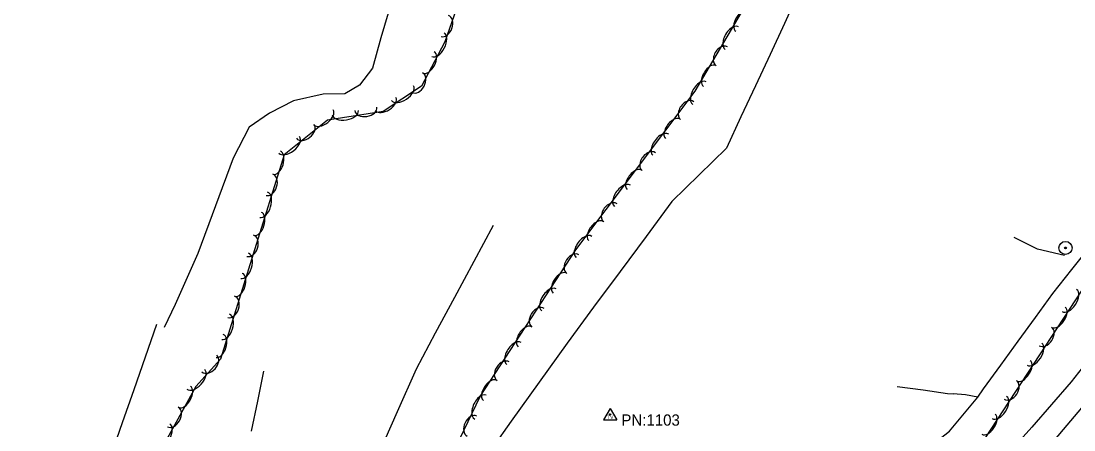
# Model space of a CAD drawing. Extents: x 1451369 to 1458940, y 1868647 to 1875095.
# Drawn here: x 1454280 to 1454748.2, y 1871820 to 1872001.9 of the extents above; entities that cross this region are included whole.
import ezdxf

# ---------------------------------------------------------------- set-up
doc = ezdxf.new("R2010")
doc.units = 0
for name, color, linetype in [('E_Const Align Station', 7, 'Continuous'), ('E_ROW Point Number', 7, 'Continuous'), ('E_Station Offset', 7, 'Continuous'), ('E_Tract Residual', 7, 'Continuous'), ('S_EDGE_PAVEMENT', 7, 'Continuous'), ('S_EXIST_ROW', 7, 'Continuous'), ('S_PAVEMENT_CROWN', 7, 'Continuous'), ('S_SECONDARY_CTL_ANNOT', 7, 'Continuous')]:
    doc.layers.add(name, color=color, linetype=linetype)

msp = doc.modelspace()

# ---------------------------------------------------------------- linework, layer by layer
at = {"layer": 'E_Const Align Station'}
for radius in [2.91, 0.411, 0.262, 0.212, 0.145, 0.0822, 0.0581]:
    msp.add_circle((1454744.49, 1871900.96), radius, dxfattribs=at)
at = {"layer": 'E_ROW Point Number'}
for points in [[(1454455.54, 1871775.31), (1454484.24, 1871834.95), (1454526.73, 1871900.15), (1454579.81, 1871970.72), (1454615.08, 1872030.7)], [(1454474.53, 1872009.99), (1454468.45, 1871992.6), (1454458.03, 1871972.85), (1454441.05, 1871961.61), (1454416.35, 1871957.74), (1454397.06, 1871942.33), (1454383.25, 1871898.18), (1454368.69, 1871851.44), (1454357.73, 1871839.38), (1454344.98, 1871816.3), (1454328.66, 1871765.24)], [(1454754.24, 1871885.99), (1454738.31, 1871861.57), (1454708.8, 1871816.51)]]:
    msp.add_lwpolyline(points, dxfattribs=at)
for centre, major_axis, ratio, start_param, end_param in [((1454468.42, 1871999.71), (1.64, 4.68), 0.683448, 3.141593, 6.283185), ((1454600.63, 1872001.94), (-2.71, -4.61), 0.540792, 3.141353, 6.282945), ((1454596.13, 1871994.3), (-2.97, -5.06), 0.550174, 3.141345, 6.282938), ((1454465.38, 1871991.33), (2.74, 5.19), 0.548524, 3.141593, 6.283185), ((1454591.67, 1871986.19), (-2.51, -4.27), 0.685428, 3.141187, 6.28278), ((1454461.25, 1871983.48), (2.49, 4.73), 0.53917, 3.141593, 6.283185), ((1454586.22, 1871977.44), (-2.71, -4.61), 0.540792, 3.141353, 6.282945), ((1454456.21, 1871974.49), (2.31, 4.38), 0.683373, 3.141593, 6.283185), ((1454449.65, 1871969.84), (4.89, 3.24), 0.548805, 3.141593, 6.283185), ((1454581.73, 1871969.8), (-2.97, -5.06), 0.550174, 3.141345, 6.282938), ((1454442.25, 1871964.94), (4.46, 2.95), 0.539446, 3.141593, 6.283185), ((1454576.25, 1871962.03), (-2.98, -3.96), 0.685311, 3.141382, 6.282975), ((1454414.57, 1871959.02), (4.18, 3.34), 0.539349, 3.141593, 6.283185), ((1454433.31, 1871962.8), (4.9, 0.77), 0.684504, 3.141593, 6.283185), ((1454424.2, 1871961.11), (5.8, 0.91), 0.549433, 3.141593, 6.283185), ((1454569.85, 1871953.96), (-3.21, -4.27), 0.540699, 3.141468, 6.283061), ((1454406.36, 1871952.8), (3.87, 3.09), 0.683599, 3.141593, 6.283185), ((1454399.29, 1871946.82), (4.59, 3.66), 0.548706, 3.141593, 6.283185), ((1454564.52, 1871946.87), (-3.53, -4.69), 0.55008, 3.141464, 6.283057), ((1454393.75, 1871938.83), (1.6, 5.1), 0.539252, 3.141593, 6.283185), ((1454559.17, 1871939.31), (-2.98, -3.96), 0.685311, 3.141382, 6.282975), ((1454552.77, 1871931.24), (-3.21, -4.27), 0.540699, 3.141468, 6.283061), ((1454390.43, 1871929.08), (1.48, 4.73), 0.683476, 3.141593, 6.283185), ((1454547.44, 1871924.15), (-3.53, -4.69), 0.55008, 3.141464, 6.283057), ((1454387.91, 1871920.16), (1.75, 5.6), 0.548607, 3.141593, 6.283185), ((1454542.08, 1871916.6), (-2.98, -3.96), 0.685311, 3.141382, 6.282975), ((1454385.26, 1871911.7), (1.6, 5.1), 0.539252, 3.141593, 6.283185), ((1454535.68, 1871908.52), (-3.21, -4.27), 0.540699, 3.141468, 6.283061), ((1454381.94, 1871901.95), (1.48, 4.73), 0.683476, 3.141593, 6.283185), ((1454530.35, 1871901.43), (-3.53, -4.69), 0.55008, 3.141464, 6.283057), ((1454379.43, 1871893.03), (1.75, 5.6), 0.548608, 3.141593, 6.283185), ((1454525.42, 1871893.77), (-2.7, -4.15), 0.685282, 3.141427, 6.283019), ((1454376.79, 1871884.56), (1.59, 5.1), 0.539252, 3.141593, 6.283185), ((1454519.58, 1871885.29), (-2.92, -4.48), 0.540677, 3.141494, 6.283087), ((1454514.74, 1871877.86), (-3.2, -4.92), 0.550057, 3.141491, 6.283084), ((1454746.21, 1871877.56), (3.21, 4.92), 0.550031, 3.141593, 6.283185), ((1454373.48, 1871874.8), (1.47, 4.73), 0.683477, 3.141593, 6.283185), ((1454509.9, 1871869.96), (-2.7, -4.15), 0.685282, 3.141427, 6.283019), ((1454741.37, 1871870.14), (2.92, 4.48), 0.540651, 3.141593, 6.283185), ((1454370.98, 1871865.89), (1.75, 5.6), 0.548608, 3.141593, 6.283185), ((1454504.06, 1871861.47), (-2.92, -4.48), 0.540677, 3.141494, 6.283087), ((1454735.52, 1871861.66), (2.72, 4.15), 0.68525, 3.141593, 6.283185), ((1454368.34, 1871857.42), (1.59, 5.1), 0.539252, 3.141593, 6.283185), ((1454499.22, 1871854.04), (-3.2, -4.92), 0.550057, 3.141491, 6.283084), ((1454730.66, 1871853.77), (3.22, 4.91), 0.550031, 3.141593, 6.283185), ((1454363.77, 1871849.56), (3.33, 3.67), 0.683439, 3.141593, 6.283185), ((1454494.38, 1871846.14), (-2.7, -4.15), 0.685282, 3.141427, 6.283019), ((1454725.81, 1871846.35), (2.93, 4.47), 0.540652, 3.141593, 6.283185), ((1454357.74, 1871842.54), (3.95, 4.34), 0.548577, 3.141593, 6.283185), ((1454488.54, 1871837.65), (-2.92, -4.48), 0.540677, 3.141494, 6.283087), ((1454719.94, 1871837.87), (2.72, 4.15), 0.68525, 3.141593, 6.283185), ((1454352.72, 1871834.69), (2.58, 4.68), 0.539168, 3.141593, 6.283185), ((1454484.31, 1871830.19), (-2.54, -5.29), 0.550027, 3.141562, 6.283155), ((1454715.09, 1871829.99), (3.22, 4.91), 0.550031, 3.141593, 6.283185), ((1454347.51, 1871825.8), (2.4, 4.34), 0.683369, 3.141593, 6.283185), ((1454480.53, 1871821.74), (-2.15, -4.47), 0.685244, 3.141543, 6.283135), ((1454710.23, 1871822.57), (2.93, 4.47), 0.540652, 3.141593, 6.283185), ((1454343.27, 1871817.57), (2.84, 5.14), 0.548521, 3.141593, 6.283185)]:
    msp.add_ellipse(centre, major_axis=major_axis, ratio=ratio, start_param=start_param, end_param=end_param, dxfattribs=at)
at = {"layer": 'E_Station Offset'}
for p, q in [((1454541.96, 1871829.55), (1454538.95, 1871824.6)), ((1454541.96, 1871829.55), (1454544.9, 1871824.6)), ((1454538.95, 1871824.6), (1454544.9, 1871824.6))]:
    msp.add_line(p, q, dxfattribs=at)
for radius in [0.311, 0.183, 0.103]:
    msp.add_circle((1454541.96, 1871826.94), radius, dxfattribs=at)
at = {"layer": 'E_Tract Residual'}
for points in [[(1454627.35, 1872018.31), (1454619.56, 1872000.84), (1454613.09, 1871986.96), (1454606.62, 1871973.08), (1454600.15, 1871959.2), (1454593.68, 1871945.32), (1454581.58, 1871933.46), (1454569.47, 1871921.59), (1454557.97, 1871906.06), (1454546.46, 1871890.53), (1454534.63, 1871874.59), (1454522.8, 1871858.64), (1454514.54, 1871847.07), (1454506.28, 1871835.51), (1454498.03, 1871823.94), (1454489.77, 1871812.38)], [(1454443.33, 1872005.36), (1454439.97, 1871994.36), (1454436.35, 1871980.98), (1454430.47, 1871973.38), (1454423.98, 1871969.44), (1454414.31, 1871969.33), (1454401.16, 1871966.36), (1454390.48, 1871960.86), (1454381.4, 1871954.66), (1454374.26, 1871940.84), (1454358.61, 1871898.53), (1454348.48, 1871875.8), (1454343.62, 1871865.57)], [(1454277.67, 1871515.79), (1454290.34, 1871508.04), (1454297.14, 1871507.25), (1454301.52, 1871508.75), (1454302.43, 1871521.24), (1454303.34, 1871533.72), (1454302.16, 1871550.52), (1454300.98, 1871567.33), (1454299.8, 1871584.13), (1454298.62, 1871600.94), (1454299.54, 1871621.72), (1454300.47, 1871642.5), (1454302.63, 1871666.52), (1454304.8, 1871690.53), (1454306.96, 1871714.55), (1454309.13, 1871738.57), (1454311.86, 1871756.12), (1454314.59, 1871773.67), (1454317.32, 1871791.22), (1454320.05, 1871808.76), (1454325.15, 1871823.36), (1454330.24, 1871837.95), (1454335.34, 1871852.55), (1454340.44, 1871867.14)]]:
    msp.add_lwpolyline(points, dxfattribs=at)
at = {"layer": 'S_EDGE_PAVEMENT'}
msp.add_lwpolyline([(1454761.69, 1871860.1), (1454746.95, 1871841.48), (1454738.24, 1871831.39), (1454729.52, 1871821.3), (1454719.14, 1871809.74), (1454710.5, 1871800.49), (1454694.1, 1871784.1), (1454684.53, 1871775.23), (1454674.42, 1871766.5), (1454666.44, 1871760.55), (1454660.2, 1871755.47), (1454648.09, 1871745.64), (1454628.58, 1871730.48), (1454609.07, 1871715.33), (1454598.13, 1871707.6), (1454587.2, 1871699.88), (1454576.26, 1871692.15), (1454565.32, 1871684.43), (1454546.17, 1871671.7), (1454541.43, 1871669), (1454540.33, 1871668.18)], dxfattribs=at)
at = {"layer": 'S_EXIST_ROW'}
for points in [[(1454707.96, 1871838.25), (1454715.68, 1871848.85), (1454723.41, 1871859.46), (1454731.14, 1871870.06), (1454738.87, 1871880.67), (1454747.32, 1871891.31), (1454755.77, 1871901.96), (1454764.23, 1871912.6), (1454772.68, 1871923.25), (1454784.03, 1871939.3), (1454795.39, 1871955.35), (1454806.74, 1871971.41), (1454818.1, 1871987.46), (1454825.89, 1871999.07), (1454833.69, 1872010.69), (1454841.48, 1872022.3), (1454849.28, 1872033.91)], [(1454438.96, 1871809.19), (1454447.38, 1871828.23), (1454455.8, 1871847.26), (1454464.38, 1871863.21), (1454472.97, 1871879.15), (1454481.56, 1871895.09), (1454490.15, 1871911.03)], [(1454744.04, 1871897.64), (1454731.96, 1871900.39), (1454721.72, 1871905.61)], [(1454382.5, 1871819.47), (1454385.24, 1871832.78), (1454387.99, 1871846.1)], [(1454589.54, 1871755.36), (1454607.61, 1871767.42), (1454623.89, 1871777.43), (1454645.48, 1871788.81), (1454666.35, 1871798.67), (1454679.64, 1871809.1), (1454692.92, 1871819.53), (1454705.5, 1871834.68), (1454700.05, 1871835.66)], [(1454669.58, 1871839.33), (1454681.23, 1871837.92), (1454692.01, 1871836.17), (1454694.53, 1871836.12)], [(1454700.05, 1871835.66), (1454694.53, 1871836.12)], [(1454705.5, 1871834.68), (1454707.96, 1871838.25)]]:
    msp.add_lwpolyline(points, dxfattribs=at)
at = {"layer": 'S_PAVEMENT_CROWN'}
msp.add_lwpolyline([(1454755.56, 1871834.56), (1454746.72, 1871824.06), (1454737.87, 1871813.57), (1454728.08, 1871803.15), (1454718.28, 1871792.74), (1454701.94, 1871776.45), (1454691.02, 1871766.3), (1454681.96, 1871758.27), (1454674.8, 1871752.2), (1454667.54, 1871746.1), (1454655.03, 1871735.92), (1454638.19, 1871723.34), (1454621.35, 1871710.76), (1454615.67, 1871706.77), (1454604.69, 1871698.97), (1454593.71, 1871691.17), (1454582.73, 1871683.38), (1454571.75, 1871675.58), (1454559.5, 1871666.75), (1454547.25, 1871657.93), (1454546.95, 1871657.7)], dxfattribs=at)

# ---------------------------------------------------------------- texts
at = {"layer": 'E_Station Offset'}
msp.add_text('TV', height=1.5, rotation=360, dxfattribs=at).set_placement((1454540.75, 1871824.93))
at = {"layer": 'S_SECONDARY_CTL_ANNOT'}
msp.add_text('PN:1103', height=5, dxfattribs=at).set_placement((1454546.96, 1871821.94))

doc.saveas('drawing.dxf')
